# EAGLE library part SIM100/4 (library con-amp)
AMP connector
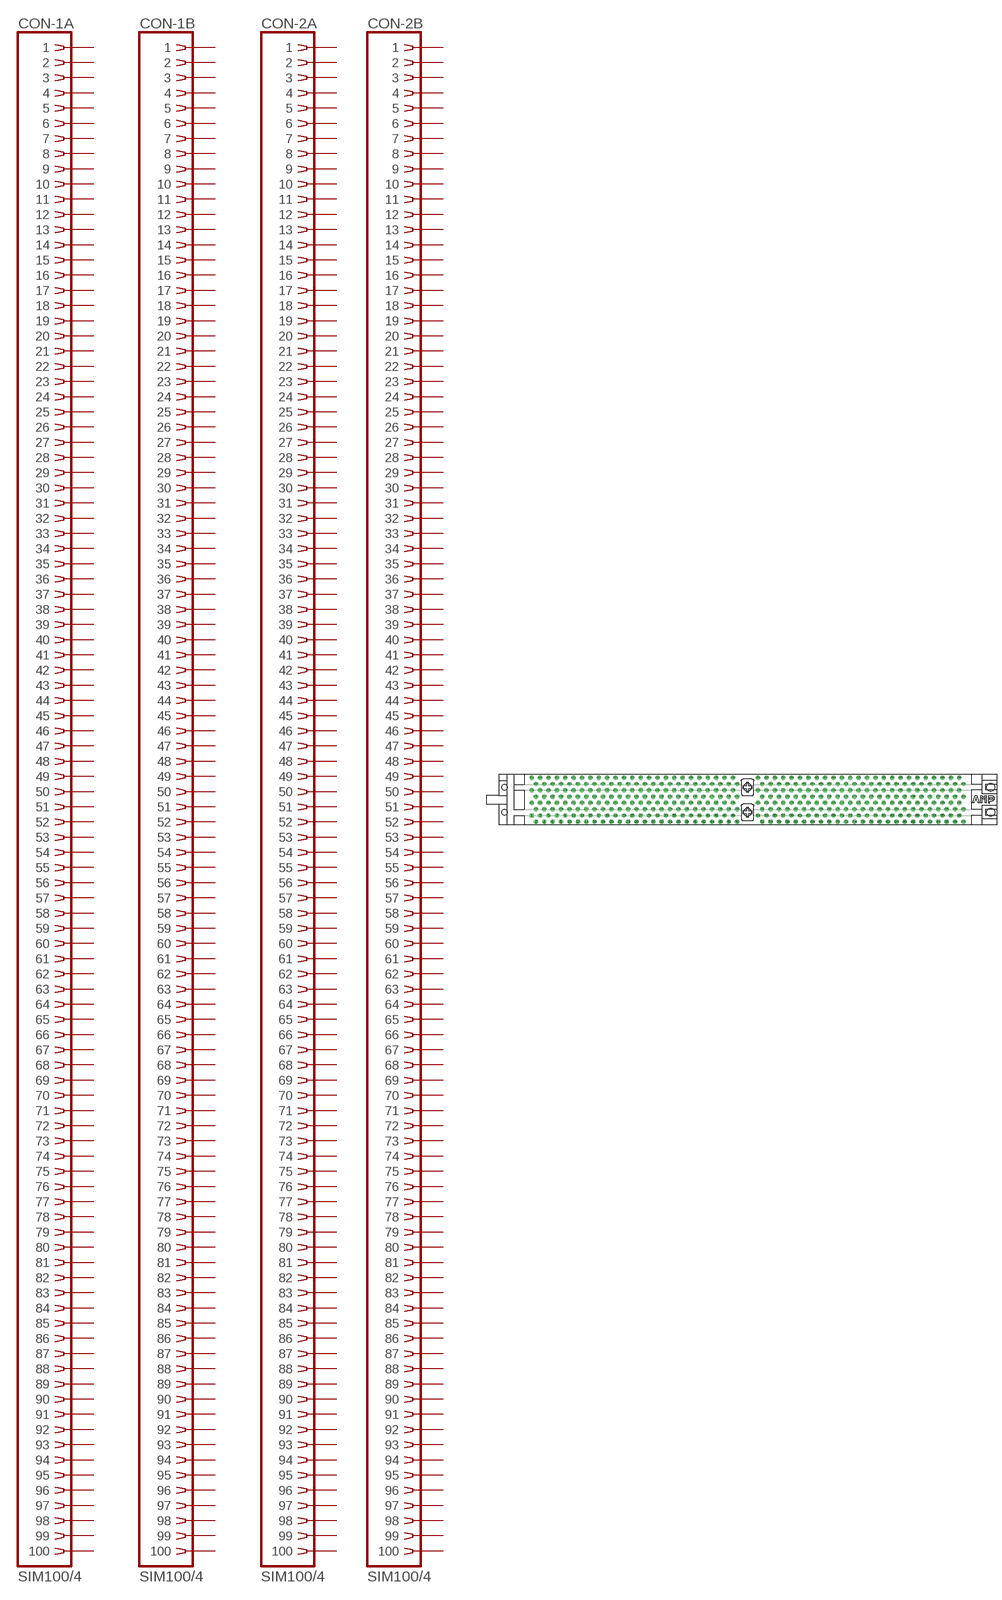
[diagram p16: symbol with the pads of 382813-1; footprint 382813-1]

Designator prefix CON; gates -1A=SIMM100 -1B=SIMM100 -2A=SIMM100 -2B=SIMM100

## SIM100/4 (OC_FARNELL: unknown; OC_NEWARK: unknown)  [382813-1]
1  -1A:1  pas
2  -1A:2  pas
3  -1A:3  pas
4  -1A:4  pas
5  -1A:5  pas
6  -1A:6  pas
7  -1A:7  pas
8  -1A:8  pas
9  -1A:9  pas
10  -1A:10  pas
11  -1A:11  pas
12  -1A:12  pas
13  -1A:13  pas
14  -1A:14  pas
15  -1A:15  pas
16  -1A:16  pas
17  -1A:17  pas
18  -1A:18  pas
19  -1A:19  pas
20  -1A:20  pas
21  -1A:21  pas
22  -1A:22  pas
23  -1A:23  pas
24  -1A:24  pas
25  -1A:25  pas
26  -1A:26  pas
27  -1A:27  pas
28  -1A:28  pas
29  -1A:29  pas
30  -1A:30  pas
31  -1A:31  pas
32  -1A:32  pas
33  -1A:33  pas
34  -1A:34  pas
35  -1A:35  pas
36  -1A:36  pas
37  -1A:37  pas
38  -1A:38  pas
39  -1A:39  pas
40  -1A:40  pas
41  -1A:41  pas
42  -1A:42  pas
43  -1A:43  pas
44  -1A:44  pas
45  -1A:45  pas
46  -1A:46  pas
47  -1A:47  pas
48  -1A:48  pas
49  -1A:49  pas
50  -1A:50  pas
51  -1A:51  pas
52  -1A:52  pas
53  -1A:53  pas
54  -1A:54  pas
55  -1A:55  pas
56  -1A:56  pas
57  -1A:57  pas
58  -1A:58  pas
59  -1A:59  pas
60  -1A:60  pas
61  -1A:61  pas
62  -1A:62  pas
63  -1A:63  pas
64  -1A:64  pas
65  -1A:65  pas
66  -1A:66  pas
67  -1A:67  pas
68  -1A:68  pas
69  -1A:69  pas
70  -1A:70  pas
71  -1A:71  pas
72  -1A:72  pas
73  -1A:73  pas
74  -1A:74  pas
75  -1A:75  pas
76  -1A:76  pas
77  -1A:77  pas
78  -1A:78  pas
79  -1A:79  pas
80  -1A:80  pas
81  -1A:81  pas
82  -1A:82  pas
83  -1A:83  pas
84  -1A:84  pas
85  -1A:85  pas
86  -1A:86  pas
87  -1A:87  pas
88  -1A:88  pas
89  -1A:89  pas
90  -1A:90  pas
91  -1A:91  pas
92  -1A:92  pas
93  -1A:93  pas
94  -1A:94  pas
95  -1A:95  pas
96  -1A:96  pas
97  -1A:97  pas
98  -1A:98  pas
99  -1A:99  pas
100  -1A:100  pas
101  -1B:1  pas
102  -1B:2  pas
103  -1B:3  pas
104  -1B:4  pas
105  -1B:5  pas
106  -1B:6  pas
107  -1B:7  pas
108  -1B:8  pas
109  -1B:9  pas
110  -1B:10  pas
111  -1B:11  pas
112  -1B:12  pas
113  -1B:13  pas
114  -1B:14  pas
115  -1B:15  pas
116  -1B:16  pas
117  -1B:17  pas
118  -1B:18  pas
119  -1B:19  pas
120  -1B:20  pas
121  -1B:21  pas
122  -1B:22  pas
123  -1B:23  pas
124  -1B:24  pas
125  -1B:25  pas
126  -1B:26  pas
127  -1B:27  pas
128  -1B:28  pas
129  -1B:29  pas
130  -1B:30  pas
131  -1B:31  pas
132  -1B:32  pas
133  -1B:33  pas
134  -1B:34  pas
135  -1B:35  pas
136  -1B:36  pas
137  -1B:37  pas
138  -1B:38  pas
139  -1B:39  pas
140  -1B:40  pas
141  -1B:41  pas
142  -1B:42  pas
143  -1B:43  pas
144  -1B:44  pas
145  -1B:45  pas
146  -1B:46  pas
147  -1B:47  pas
148  -1B:48  pas
149  -1B:49  pas
150  -1B:50  pas
151  -1B:51  pas
152  -1B:52  pas
153  -1B:53  pas
154  -1B:54  pas
155  -1B:55  pas
156  -1B:56  pas
157  -1B:57  pas
158  -1B:58  pas
159  -1B:59  pas
160  -1B:60  pas
161  -1B:61  pas
162  -1B:62  pas
163  -1B:63  pas
164  -1B:64  pas
165  -1B:65  pas
166  -1B:66  pas
167  -1B:67  pas
168  -1B:68  pas
169  -1B:69  pas
170  -1B:70  pas
171  -1B:71  pas
172  -1B:72  pas
173  -1B:73  pas
174  -1B:74  pas
175  -1B:75  pas
176  -1B:76  pas
177  -1B:77  pas
178  -1B:78  pas
179  -1B:79  pas
180  -1B:80  pas
181  -1B:81  pas
182  -1B:82  pas
183  -1B:83  pas
184  -1B:84  pas
185  -1B:85  pas
186  -1B:86  pas
187  -1B:87  pas
188  -1B:88  pas
189  -1B:89  pas
190  -1B:90  pas
191  -1B:91  pas
192  -1B:92  pas
193  -1B:93  pas
194  -1B:94  pas
195  -1B:95  pas
196  -1B:96  pas
197  -1B:97  pas
198  -1B:98  pas
199  -1B:99  pas
200  -1B:100  pas
201  -2A:1  pas
202  -2A:2  pas
203  -2A:3  pas
204  -2A:4  pas
205  -2A:5  pas
206  -2A:6  pas
207  -2A:7  pas
208  -2A:8  pas
209  -2A:9  pas
210  -2A:10  pas
211  -2A:11  pas
212  -2A:12  pas
213  -2A:13  pas
214  -2A:14  pas
215  -2A:15  pas
216  -2A:16  pas
217  -2A:17  pas
218  -2A:18  pas
219  -2A:19  pas
220  -2A:20  pas
221  -2A:21  pas
222  -2A:22  pas
223  -2A:23  pas
224  -2A:24  pas
225  -2A:25  pas
226  -2A:26  pas
227  -2A:27  pas
228  -2A:28  pas
229  -2A:29  pas
230  -2A:30  pas
231  -2A:31  pas
232  -2A:32  pas
233  -2A:33  pas
234  -2A:34  pas
235  -2A:35  pas
236  -2A:36  pas
237  -2A:37  pas
238  -2A:38  pas
239  -2A:39  pas
240  -2A:40  pas
241  -2A:41  pas
242  -2A:42  pas
243  -2A:43  pas
244  -2A:44  pas
245  -2A:45  pas
246  -2A:46  pas
247  -2A:47  pas
248  -2A:48  pas
249  -2A:49  pas
250  -2A:50  pas
251  -2A:51  pas
252  -2A:52  pas
253  -2A:53  pas
254  -2A:54  pas
255  -2A:55  pas
256  -2A:56  pas
257  -2A:57  pas
258  -2A:58  pas
259  -2A:59  pas
260  -2A:60  pas
261  -2A:61  pas
262  -2A:62  pas
263  -2A:63  pas
264  -2A:64  pas
265  -2A:65  pas
266  -2A:66  pas
267  -2A:67  pas
268  -2A:68  pas
269  -2A:69  pas
270  -2A:70  pas
271  -2A:71  pas
272  -2A:72  pas
273  -2A:73  pas
274  -2A:74  pas
275  -2A:75  pas
276  -2A:76  pas
277  -2A:77  pas
278  -2A:78  pas
279  -2A:79  pas
280  -2A:80  pas
281  -2A:81  pas
282  -2A:82  pas
283  -2A:83  pas
284  -2A:84  pas
285  -2A:85  pas
286  -2A:86  pas
287  -2A:87  pas
288  -2A:88  pas
289  -2A:89  pas
290  -2A:90  pas
291  -2A:91  pas
292  -2A:92  pas
293  -2A:93  pas
294  -2A:94  pas
295  -2A:95  pas
296  -2A:96  pas
297  -2A:97  pas
298  -2A:98  pas
299  -2A:99  pas
300  -2A:100  pas
301  -2B:1  pas
302  -2B:2  pas
303  -2B:3  pas
304  -2B:4  pas
305  -2B:5  pas
306  -2B:6  pas
307  -2B:7  pas
308  -2B:8  pas
309  -2B:9  pas
310  -2B:10  pas
311  -2B:11  pas
312  -2B:12  pas
313  -2B:13  pas
314  -2B:14  pas
315  -2B:15  pas
316  -2B:16  pas
317  -2B:17  pas
318  -2B:18  pas
319  -2B:19  pas
320  -2B:20  pas
321  -2B:21  pas
322  -2B:22  pas
323  -2B:23  pas
324  -2B:24  pas
325  -2B:25  pas
326  -2B:26  pas
327  -2B:27  pas
328  -2B:28  pas
329  -2B:29  pas
330  -2B:30  pas
331  -2B:31  pas
332  -2B:32  pas
333  -2B:33  pas
334  -2B:34  pas
335  -2B:35  pas
336  -2B:36  pas
337  -2B:37  pas
338  -2B:38  pas
339  -2B:39  pas
340  -2B:40  pas
341  -2B:41  pas
342  -2B:42  pas
343  -2B:43  pas
344  -2B:44  pas
345  -2B:45  pas
346  -2B:46  pas
347  -2B:47  pas
348  -2B:48  pas
349  -2B:49  pas
350  -2B:50  pas
351  -2B:51  pas
352  -2B:52  pas
353  -2B:53  pas
354  -2B:54  pas
355  -2B:55  pas
356  -2B:56  pas
357  -2B:57  pas
358  -2B:58  pas
359  -2B:59  pas
360  -2B:60  pas
361  -2B:61  pas
362  -2B:62  pas
363  -2B:63  pas
364  -2B:64  pas
365  -2B:65  pas
366  -2B:66  pas
367  -2B:67  pas
368  -2B:68  pas
369  -2B:69  pas
370  -2B:70  pas
371  -2B:71  pas
372  -2B:72  pas
373  -2B:73  pas
374  -2B:74  pas
375  -2B:75  pas
376  -2B:76  pas
377  -2B:77  pas
378  -2B:78  pas
379  -2B:79  pas
380  -2B:80  pas
381  -2B:81  pas
382  -2B:82  pas
383  -2B:83  pas
384  -2B:84  pas
385  -2B:85  pas
386  -2B:86  pas
387  -2B:87  pas
388  -2B:88  pas
389  -2B:89  pas
390  -2B:90  pas
391  -2B:91  pas
392  -2B:92  pas
393  -2B:93  pas
394  -2B:94  pas
395  -2B:95  pas
396  -2B:96  pas
397  -2B:97  pas
398  -2B:98  pas
399  -2B:99  pas
400  -2B:100  pas

## Footprint 382813-1 (pad centres in mm)
DIMM I Dual Read Out
drill 0.813 square: 1 -65.405,-4.763
drill 0.813 octagon: 2 -64.135,-6.668; 3 -62.865,-4.763; 4 -61.595,-6.668; 5 -60.325,-4.763; 6 -59.055,-6.668; 7 -57.785,-4.763; 8 -56.515,-6.668; 9 -55.245,-4.763; 10 -53.975,-6.668; 11 -52.705,-4.763; 12 -51.435,-6.668; 13 -50.165,-4.763; 14 -48.895,-6.668; 15 -47.625,-4.763; 16 -46.355,-6.668; 17 -45.085,-4.763; 18 -43.815,-6.668; 19 -42.545,-4.763; 20 -41.275,-6.668; 21 -40.005,-4.763; 22 -38.735,-6.668; 23 -37.465,-4.763; 24 -36.195,-6.668; 25 -34.925,-4.763; 26 -33.655,-6.668; 27 -32.385,-4.763; 28 -31.115,-6.668; 29 -29.845,-4.763; 30 -28.575,-6.668; 31 -27.305,-4.763; 32 -26.035,-6.668; 33 -24.765,-4.763; 34 -23.495,-6.668; 35 -22.225,-4.763; 36 -20.955,-6.668; 37 -19.685,-4.763; 38 -18.415,-6.668; 39 -17.145,-4.763; 40 -15.875,-6.668; 41 -14.605,-4.763; 42 -13.335,-6.668; 43 -12.065,-4.763; 44 -10.795,-6.668; 45 -9.525,-4.763; 46 -8.255,-6.668; 47 -6.985,-4.763; 48 -5.715,-6.668; 49 -4.445,-4.763; 50 -3.175,-6.668; 51 3.175,-4.763; 52 4.445,-6.668; 53 5.715,-4.763; 54 6.985,-6.668; 55 8.255,-4.763; 56 9.525,-6.668; 57 10.795,-4.763; 58 12.065,-6.668; 59 13.335,-4.763; 60 14.605,-6.668; 61 15.875,-4.763; 62 17.145,-6.668; 63 18.415,-4.763; 64 19.685,-6.668; 65 20.955,-4.763; 66 22.225,-6.668; 67 23.495,-4.763; 68 24.765,-6.668; 69 26.035,-4.763; 70 27.305,-6.668; 71 28.575,-4.763; 72 29.845,-6.668; 73 31.115,-4.763; 74 32.385,-6.668; 75 33.655,-4.763; 76 34.925,-6.668; 77 36.195,-4.763; 78 37.465,-6.668; 79 38.735,-4.763; 80 40.005,-6.668; 81 41.275,-4.763; 82 42.545,-6.668; 83 43.815,-4.763; 84 45.085,-6.668; 85 46.355,-4.763; 86 47.625,-6.668; 87 48.895,-4.763; 88 50.165,-6.668; 89 51.435,-4.763; 90 52.705,-6.668; 91 53.975,-4.763; 92 55.245,-6.668; 93 56.515,-4.763; 94 57.785,-6.668; 95 59.055,-4.763; 96 60.325,-6.668; 97 61.595,-4.763; 98 62.865,-6.668; 99 64.135,-4.763; 100 65.405,-6.668; 101 -65.405,-0.953; 102 -64.135,-2.857; 103 -62.865,-0.953; 104 -61.595,-2.857; 105 -60.325,-0.953; 106 -59.055,-2.857; 107 -57.785,-0.953; 108 -56.515,-2.857; 109 -55.245,-0.953; 110 -53.975,-2.857; 111 -52.705,-0.953; 112 -51.435,-2.857; 113 -50.165,-0.953; 114 -48.895,-2.857; 115 -47.625,-0.953; 116 -46.355,-2.857; 117 -45.085,-0.953; 118 -43.815,-2.857; 119 -42.545,-0.953; 120 -41.275,-2.857; 121 -40.005,-0.953; 122 -38.735,-2.857; 123 -37.465,-0.953; 124 -36.195,-2.857; 125 -34.925,-0.953; 126 -33.655,-2.857; 127 -32.385,-0.953; 128 -31.115,-2.857; 129 -29.845,-0.953; 130 -28.575,-2.857; 131 -27.305,-0.953; 132 -26.035,-2.857; 133 -24.765,-0.953; 134 -23.495,-2.857; 135 -22.225,-0.953; 136 -20.955,-2.857; 137 -19.685,-0.953; 138 -18.415,-2.857; 139 -17.145,-0.953; 140 -15.875,-2.857; 141 -14.605,-0.953; 142 -13.335,-2.857; 143 -12.065,-0.953; 144 -10.795,-2.857; 145 -9.525,-0.953; 146 -8.255,-2.857; 147 -6.985,-0.953; 148 -5.715,-2.857; 149 -4.445,-0.953; 150 -3.175,-2.857; 151 3.175,-0.953; 152 4.445,-2.857; 153 5.715,-0.953; 154 6.985,-2.857; 155 8.255,-0.953; 156 9.525,-2.857; 157 10.795,-0.953; 158 12.065,-2.857; 159 13.335,-0.953; 160 14.605,-2.857; 161 15.875,-0.953; 162 17.145,-2.857; 163 18.415,-0.953; 164 19.685,-2.857; 165 20.955,-0.953; 166 22.225,-2.857; 167 23.495,-0.953; 168 24.765,-2.857; 169 26.035,-0.953; 170 27.305,-2.857; 171 28.575,-0.953; 172 29.845,-2.857; 173 31.115,-0.953; 174 32.385,-2.857; 175 33.655,-0.953; 176 34.925,-2.857; 177 36.195,-0.953; 178 37.465,-2.857; 179 38.735,-0.953; 180 40.005,-2.857; 181 41.275,-0.953; 182 42.545,-2.857; 183 43.815,-0.953; 184 45.085,-2.857; 185 46.355,-0.953; 186 47.625,-2.857; 187 48.895,-0.953; 188 50.165,-2.857; 189 51.435,-0.953; 190 52.705,-2.857; 191 53.975,-0.953; 192 55.245,-2.857; 193 56.515,-0.953; 194 57.785,-2.857; 195 59.055,-0.953; 196 60.325,-2.857; 197 61.595,-0.953; 198 62.865,-2.857; 199 64.135,-0.953; 200 65.405,-2.857; 201 -65.405,2.857; 202 -64.135,0.953; 203 -62.865,2.857; 204 -61.595,0.953; 205 -60.325,2.857; 206 -59.055,0.953; 207 -57.785,2.857; 208 -56.515,0.953; 209 -55.245,2.857; 210 -53.975,0.953; 211 -52.705,2.857; 212 -51.435,0.953; 213 -50.165,2.857; 214 -48.895,0.953; 215 -47.625,2.857; 216 -46.355,0.953; 217 -45.085,2.857; 218 -43.815,0.953; 219 -42.545,2.857; 220 -41.275,0.953; 221 -40.005,2.857; 222 -38.735,0.953; 223 -37.465,2.857; 224 -36.195,0.953; 225 -34.925,2.857; 226 -33.655,0.953; 227 -32.385,2.857; 228 -31.115,0.953; 229 -29.845,2.857; 230 -28.575,0.953; 231 -27.305,2.857; 232 -26.035,0.953; 233 -24.765,2.857; 234 -23.495,0.953; 235 -22.225,2.857; 236 -20.955,0.953; 237 -19.685,2.857; 238 -18.415,0.953; 239 -17.145,2.857; 240 -15.875,0.953; 241 -14.605,2.857; 242 -13.335,0.953; 243 -12.065,2.857; 244 -10.795,0.953; 245 -9.525,2.857; 246 -8.255,0.953; 247 -6.985,2.857; 248 -5.715,0.953; 249 -4.445,2.857; 250 -3.175,0.953; 251 3.175,2.857; 252 4.445,0.953; 253 5.715,2.857; 254 6.985,0.953; 255 8.255,2.857; 256 9.525,0.953; 257 10.795,2.857; 258 12.065,0.953; 259 13.335,2.857; 260 14.605,0.953; 261 15.875,2.857; 262 17.145,0.953; 263 18.415,2.857; 264 19.685,0.953; 265 20.955,2.857; 266 22.225,0.953; 267 23.495,2.857; 268 24.765,0.953; 269 26.035,2.857; 270 27.305,0.953; 271 28.575,2.857; 272 29.845,0.953; 273 31.115,2.857; 274 32.385,0.953; 275 33.655,2.857; 276 34.925,0.953; 277 36.195,2.857; 278 37.465,0.953; 279 38.735,2.857; 280 40.005,0.953; 281 41.275,2.857; 282 42.545,0.953; 283 43.815,2.857; 284 45.085,0.953; 285 46.355,2.857; 286 47.625,0.953; 287 48.895,2.857; 288 50.165,0.953; 289 51.435,2.857; 290 52.705,0.953; 291 53.975,2.857; 292 55.245,0.953; 293 56.515,2.857; 294 57.785,0.953; 295 59.055,2.857; 296 60.325,0.953; 297 61.595,2.857; 298 62.865,0.953; 299 64.135,2.857; 300 65.405,0.953; 301 -65.405,6.668; 302 -64.135,4.763; 303 -62.865,6.668; 304 -61.595,4.763; 305 -60.325,6.668; 306 -59.055,4.763; 307 -57.785,6.668; 308 -56.515,4.763; 309 -55.245,6.668; 310 -53.975,4.763; 311 -52.705,6.668; 312 -51.435,4.763; 313 -50.165,6.668; 314 -48.895,4.763; 315 -47.625,6.668; 316 -46.355,4.763; 317 -45.085,6.668; 318 -43.815,4.763; 319 -42.545,6.668; 320 -41.275,4.763; 321 -40.005,6.668; 322 -38.735,4.763; 323 -37.465,6.668; 324 -36.195,4.763; 325 -34.925,6.668; 326 -33.655,4.763; 327 -32.385,6.668; 328 -31.115,4.763; 329 -29.845,6.668; 330 -28.575,4.763; 331 -27.305,6.668; 332 -26.035,4.763; 333 -24.765,6.668; 334 -23.495,4.763; 335 -22.225,6.668; 336 -20.955,4.763; 337 -19.685,6.668; 338 -18.415,4.763; 339 -17.145,6.668; 340 -15.875,4.763; 341 -14.605,6.668; 342 -13.335,4.763; 343 -12.065,6.668; 344 -10.795,4.763; 345 -9.525,6.668; 346 -8.255,4.763; 347 -6.985,6.668; 348 -5.715,4.763; 349 -4.445,6.668; 350 -3.175,4.763; 351 3.175,6.668; 352 4.445,4.763; 353 5.715,6.668; 354 6.985,4.763; 355 8.255,6.668; 356 9.525,4.763; 357 10.795,6.668; 358 12.065,4.763; 359 13.335,6.668; 360 14.605,4.763; 361 15.875,6.668; 362 17.145,4.763; 363 18.415,6.668; 364 19.685,4.763; 365 20.955,6.668; 366 22.225,4.763; 367 23.495,6.668; 368 24.765,4.763; 369 26.035,6.668; 370 27.305,4.763; 371 28.575,6.668; 372 29.845,4.763; 373 31.115,6.668; 374 32.385,4.763; 375 33.655,6.668; 376 34.925,4.763; 377 36.195,6.668; 378 37.465,4.763; 379 38.735,6.668; 380 40.005,4.763; 381 41.275,6.668; 382 42.545,4.763; 383 43.815,6.668; 384 45.085,4.763; 385 46.355,6.668; 386 47.625,4.763; 387 48.895,6.668; 388 50.165,4.763; 389 51.435,6.668; 390 52.705,4.763; 391 53.975,6.668; 392 55.245,4.763; 393 56.515,6.668; 394 57.785,4.763; 395 59.055,6.668; 396 60.325,4.763; 397 61.595,6.668; 398 62.865,4.763; 399 64.135,6.668; 400 65.405,4.763
hole 1.575 at -73.66,-3.81
hole 2.362 at 0,-3.81
hole 2.362 at 73.66,-3.81
hole 1.575 at -73.66,3.81
hole 2.362 at 0,3.81
hole 2.362 at 73.66,3.81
